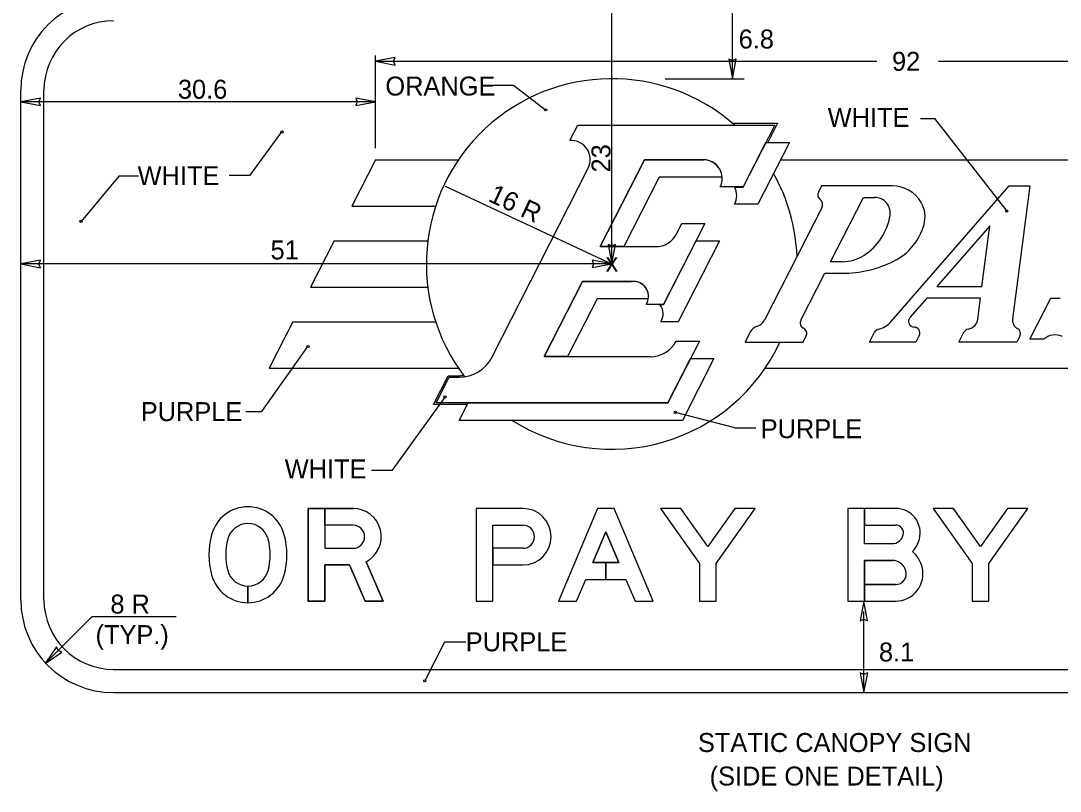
# Model space of a CAD drawing. Extents: x 319706 to 320449, y 1621775 to 1622117.
# Drawn here: x 319821.8 to 319898.5, y 1621852.1 to 1621908.9 of the extents above; entities that cross this region are included whole.
import ezdxf

# ---------------------------------------------------------------- set-up
doc = ezdxf.new("R2010")
doc.units = 0
for name, color, linetype in [('1', 7, 'Continuous'), ('52', 7, 'Continuous'), ('GSBWFill', 7, 'Continuous'), ('GSColorFill', 7, 'Continuous'), ('GSOutline', 7, 'Continuous'), ('SignPanel', 7, 'Continuous')]:
    doc.layers.add(name, color=color, linetype=linetype)

msp = doc.modelspace()

# ---------------------------------------------------------------- linework, layer by layer
at = {"layer": '1'}
for p, q in [((319865.435, 1621890.975), (319865.435, 1621910.64)), ((319874.341, 1621904.654), (319874.341, 1621910.639)), ((319847.993, 1621899.525), (319847.993, 1621906.365)), ((319847.993, 1621905.938), (319884.997, 1621905.938)), ((319889.548, 1621905.938), (319926.653, 1621905.938)), ((319869.368, 1621904.654), (319875.196, 1621904.654)), ((319856.646, 1621904.176), (319858.193, 1621904.176)), ((319858.193, 1621904.176), (319860.552, 1621902.355)), ((319847.993, 1621902.945), (319821.83, 1621902.945)), ((319888.22, 1621901.716), (319889.238, 1621901.716)), ((319889.238, 1621901.716), (319894.572, 1621894.876)), ((319838.762, 1621897.524), (319841.1, 1621900.723)), ((319829.062, 1621897.454), (319826.277, 1621894.117)), ((319830.508, 1621897.454), (319829.062, 1621897.454)), ((319837.215, 1621897.524), (319838.762, 1621897.524)), ((319865.435, 1621890.974), (319853.158, 1621896.699)), ((319850.398, 1621890.975), (319821.83, 1621890.975)), ((319865.435, 1621890.975), (319850.398, 1621890.975)), ((319839.622, 1621880.096), (319843.019, 1621884.886)), ((319849.249, 1621875.759), (319853.128, 1621881.149)), ((319838.436, 1621880.096), (319839.622, 1621880.096)), ((319874.522, 1621878.868), (319870.131, 1621880.017)), ((319874.522, 1621878.868), (319876.07, 1621878.868)), ((319847.701, 1621875.759), (319849.249, 1621875.759)), ((319884.034, 1621859.339), (319884.034, 1621865.324)), ((319823.628, 1621861.492), (319827.091, 1621864.955)), ((319827.091, 1621864.955), (319833.282, 1621864.955)), ((319853.1, 1621863.057), (319851.628, 1621860.204)), ((319854.662, 1621863.057), (319853.1, 1621863.057))]:
    msp.add_line(p, q, dxfattribs=at)
for centre in [(319860.552, 1621902.354), (319841.1, 1621900.722), (319894.571, 1621894.875), (319826.277, 1621894.116), (319843.019, 1621884.884), (319853.128, 1621881.148), (319870.131, 1621880.015), (319870.131, 1621880.015), (319851.628, 1621860.204)]:
    msp.add_circle(centre, 0.0855, dxfattribs=at)
at = {"layer": '52'}
for p, q in [((319849.443, 1621906.208), (319847.993, 1621905.938)), ((319847.993, 1621905.938), (319849.443, 1621905.658)), ((319849.333, 1621905.938), (319849.443, 1621906.208)), ((319849.443, 1621905.658), (319849.333, 1621905.938)), ((319874.341, 1621905.994), (319874.071, 1621906.104)), ((319874.071, 1621906.104), (319874.341, 1621904.654)), ((319874.341, 1621904.654), (319874.621, 1621906.104)), ((319874.621, 1621906.104), (319874.341, 1621905.994)), ((319823.28, 1621903.215), (319821.83, 1621902.945)), ((319821.83, 1621902.945), (319823.28, 1621902.665)), ((319823.17, 1621902.945), (319823.28, 1621903.215)), ((319823.28, 1621902.665), (319823.17, 1621902.945)), ((319847.993, 1621902.945), (319846.543, 1621903.225)), ((319846.543, 1621903.225), (319846.653, 1621902.945)), ((319846.653, 1621902.945), (319846.543, 1621902.675)), ((319846.543, 1621902.675), (319847.993, 1621902.945)), ((319865.435, 1621892.315), (319865.165, 1621892.425)), ((319865.165, 1621892.425), (319865.435, 1621890.975)), ((319865.435, 1621890.975), (319865.715, 1621892.425)), ((319865.715, 1621892.425), (319865.435, 1621892.315)), ((319823.28, 1621891.245), (319821.83, 1621890.975)), ((319823.17, 1621890.975), (319823.28, 1621891.245)), ((319865.435, 1621890.975), (319863.985, 1621891.255)), ((319863.985, 1621891.255), (319864.095, 1621890.975)), ((319821.83, 1621890.975), (319823.28, 1621890.695)), ((319823.28, 1621890.695), (319823.17, 1621890.975)), ((319864.095, 1621890.975), (319863.985, 1621890.705)), ((319863.985, 1621890.705), (319865.435, 1621890.975)), ((319884.034, 1621866.088), (319883.754, 1621864.638)), ((319884.304, 1621864.638), (319884.034, 1621866.088)), ((319883.754, 1621864.638), (319884.034, 1621864.748)), ((319884.034, 1621864.748), (319884.304, 1621864.638)), ((319824.463, 1621862.708), (319823.628, 1621861.492)), ((319823.628, 1621861.492), (319824.851, 1621862.32)), ((319824.576, 1621862.44), (319824.463, 1621862.708)), ((319824.851, 1621862.32), (319824.576, 1621862.44)), ((319884.034, 1621860.679), (319883.764, 1621860.789)), ((319883.764, 1621860.789), (319884.034, 1621859.339)), ((319884.034, 1621859.339), (319884.314, 1621860.789)), ((319884.314, 1621860.789), (319884.034, 1621860.679))]:
    msp.add_line(p, q, dxfattribs=at)
at = {"layer": 'GSBWFill'}
for p, q in [((319856.649, 1621871.698), (319858.873, 1621871.698)), ((319838.587, 1621867.199), (319838.587, 1621865.968)), ((319838.588, 1621865.968), (319838.588, 1621867.199))]:
    msp.add_line(p, q, dxfattribs=at)
for points in [[(319847.316, 1621868.997), (319848.576, 1621866.088), (319847.234, 1621866.088), (319846.079, 1621868.756), (319844.266, 1621868.756), (319844.266, 1621866.088), (319843.034, 1621866.088), (319843.034, 1621872.929), (319844.266, 1621872.929), (319844.266, 1621869.987), (319846.342, 1621869.987)], [(319844.266, 1621871.698), (319844.266, 1621872.929), (319846.342, 1621872.929)], [(319858.873, 1621872.929), (319855.418, 1621872.929), (319855.418, 1621866.088), (319856.649, 1621866.088), (319856.649, 1621871.698)], [(319886.111, 1621870.329), (319884.084, 1621870.329), (319884.084, 1621872.929), (319882.852, 1621872.929), (319882.852, 1621866.088), (319884.084, 1621866.088)], [(319886.376, 1621872.929), (319884.084, 1621872.929), (319884.084, 1621871.698), (319886.376, 1621871.698)], [(319846.342, 1621871.698), (319844.266, 1621871.698)], [(319858.873, 1621869.987), (319856.649, 1621869.987), (319856.649, 1621868.756), (319858.873, 1621868.756)], [(319884.084, 1621866.088), (319884.084, 1621869.098), (319886.111, 1621869.098)], [(319886.376, 1621867.319), (319884.084, 1621867.319), (319884.084, 1621866.088), (319886.376, 1621866.088)]]:
    msp.add_lwpolyline(points, dxfattribs=at)
for points in [[(319865.957, 1621868.927), (319864.996, 1621868.927), (319864.996, 1621867.695), (319866.474, 1621867.695), (319867.149, 1621866.088), (319868.485, 1621866.088), (319865.612, 1621872.929), (319864.38, 1621872.929), (319861.507, 1621866.088), (319862.842, 1621866.088), (319863.518, 1621867.695), (319864.996, 1621867.695), (319864.996, 1621868.927), (319864.035, 1621868.927), (319864.996, 1621871.215)], [(319873.137, 1621868.858), (319876.011, 1621872.929), (319874.503, 1621872.929), (319872.522, 1621870.122), (319870.54, 1621872.929), (319869.032, 1621872.929), (319871.906, 1621868.858), (319871.906, 1621866.088), (319873.137, 1621866.088)], [(319893.251, 1621868.858), (319896.125, 1621872.929), (319894.618, 1621872.929), (319892.636, 1621870.122), (319890.654, 1621872.929), (319889.147, 1621872.929), (319892.02, 1621868.858), (319892.02, 1621866.088), (319893.251, 1621866.088)]]:
    msp.add_lwpolyline(points, close=True, dxfattribs=at)
for centre, radius, start, end in [((319838.587, 1621870.276), 2.773, 14.96177, 165.03823), ((319846.342, 1621870.843), 2.087, 297.837, 90), ((319886.376, 1621871.116), 1.813, 345.52249, 90), ((319838.587, 1621870.276), 1.541, 14.96177, 165.03823), ((319846.342, 1621870.843), 0.855, 270, 90), ((319886.376, 1621871.116), 0.582, 345.52249, 90), ((319841.461, 1621869.508), 5.747, 165.03823, 194.96177), ((319841.461, 1621869.508), 4.515, 165.03823, 194.96177), ((319835.714, 1621869.508), 4.515, 345.03823, 14.96177), ((319835.714, 1621869.508), 5.747, 345.03823, 14.96177), ((319886.111, 1621871.185), 0.855, 270, 345.52249), ((319886.111, 1621871.185), 2.087, 316.7114, 345.52249), ((319886.111, 1621868.037), 2.292, 14.47751, 48.4921), ((319886.111, 1621868.037), 1.06, 14.47751, 90), ((319838.587, 1621868.741), 1.541, 194.96177, 270), ((319838.587, 1621868.741), 1.541, 270.01272, 345.03823), ((319886.376, 1621868.106), 2.018, 270, 14.47751), ((319886.376, 1621868.106), 0.787, 270, 14.47751), ((319838.587, 1621868.741), 2.773, 194.96177, 270), ((319838.587, 1621868.741), 2.773, 270.00707, 345.03823)]:
    msp.add_arc(centre, radius, start, end, dxfattribs=at)
for major_axis in [(0, 2.087), (0, 0.855)]:
    msp.add_ellipse((319858.873, 1621870.843), major_axis=major_axis, ratio=0.999994, start_param=3.141593, end_param=6.283185, dxfattribs=at)
at = {"layer": 'GSColorFill'}
for p, q in [((319856.649, 1621871.698), (319858.873, 1621871.698)), ((319838.587, 1621867.199), (319838.587, 1621865.968)), ((319838.588, 1621865.968), (319838.588, 1621867.199))]:
    msp.add_line(p, q, dxfattribs=at)
for points in [[(319847.316, 1621868.997), (319848.576, 1621866.088), (319847.234, 1621866.088), (319846.079, 1621868.756), (319844.266, 1621868.756), (319844.266, 1621866.088), (319843.034, 1621866.088), (319843.034, 1621872.929), (319844.266, 1621872.929), (319844.266, 1621869.987), (319846.342, 1621869.987)], [(319844.266, 1621871.698), (319844.266, 1621872.929), (319846.342, 1621872.929)], [(319858.873, 1621872.929), (319855.418, 1621872.929), (319855.418, 1621866.088), (319856.649, 1621866.088), (319856.649, 1621871.698)], [(319886.111, 1621870.329), (319884.084, 1621870.329), (319884.084, 1621872.929), (319882.852, 1621872.929), (319882.852, 1621866.088), (319884.084, 1621866.088)], [(319886.376, 1621872.929), (319884.084, 1621872.929), (319884.084, 1621871.698), (319886.376, 1621871.698)], [(319846.342, 1621871.698), (319844.266, 1621871.698)], [(319858.873, 1621869.987), (319856.649, 1621869.987), (319856.649, 1621868.756), (319858.873, 1621868.756)], [(319884.084, 1621866.088), (319884.084, 1621869.098), (319886.111, 1621869.098)], [(319886.376, 1621867.319), (319884.084, 1621867.319), (319884.084, 1621866.088), (319886.376, 1621866.088)]]:
    msp.add_lwpolyline(points, dxfattribs=at)
for points in [[(319865.957, 1621868.927), (319864.996, 1621868.927), (319864.996, 1621867.695), (319866.474, 1621867.695), (319867.149, 1621866.088), (319868.485, 1621866.088), (319865.612, 1621872.929), (319864.38, 1621872.929), (319861.507, 1621866.088), (319862.842, 1621866.088), (319863.518, 1621867.695), (319864.996, 1621867.695), (319864.996, 1621868.927), (319864.035, 1621868.927), (319864.996, 1621871.215)], [(319873.137, 1621868.858), (319876.011, 1621872.929), (319874.503, 1621872.929), (319872.522, 1621870.122), (319870.54, 1621872.929), (319869.032, 1621872.929), (319871.906, 1621868.858), (319871.906, 1621866.088), (319873.137, 1621866.088)], [(319893.251, 1621868.858), (319896.125, 1621872.929), (319894.618, 1621872.929), (319892.636, 1621870.122), (319890.654, 1621872.929), (319889.147, 1621872.929), (319892.02, 1621868.858), (319892.02, 1621866.088), (319893.251, 1621866.088)]]:
    msp.add_lwpolyline(points, close=True, dxfattribs=at)
for centre, radius, start, end in [((319838.587, 1621870.276), 2.773, 14.96177, 165.03823), ((319846.342, 1621870.843), 2.087, 297.837, 90), ((319886.376, 1621871.116), 1.813, 345.52249, 90), ((319838.587, 1621870.276), 1.541, 14.96177, 165.03823), ((319846.342, 1621870.843), 0.855, 270, 90), ((319886.376, 1621871.116), 0.582, 345.52249, 90), ((319841.461, 1621869.508), 5.747, 165.03823, 194.96177), ((319841.461, 1621869.508), 4.515, 165.03823, 194.96177), ((319835.714, 1621869.508), 4.515, 345.03823, 14.96177), ((319835.714, 1621869.508), 5.747, 345.03823, 14.96177), ((319886.111, 1621871.185), 0.855, 270, 345.52249), ((319886.111, 1621871.185), 2.087, 316.7114, 345.52249), ((319886.111, 1621868.037), 2.292, 14.47751, 48.4921), ((319886.111, 1621868.037), 1.06, 14.47751, 90), ((319838.587, 1621868.741), 1.541, 194.96177, 270), ((319838.587, 1621868.741), 1.541, 270.01272, 345.03823), ((319886.376, 1621868.106), 2.018, 270, 14.47751), ((319886.376, 1621868.106), 0.787, 270, 14.47751), ((319838.587, 1621868.741), 2.773, 194.96177, 270), ((319838.587, 1621868.741), 2.773, 270.00707, 345.03823)]:
    msp.add_arc(centre, radius, start, end, dxfattribs=at)
for major_axis in [(0, 2.087), (0, 0.855)]:
    msp.add_ellipse((319858.873, 1621870.843), major_axis=major_axis, ratio=0.999994, start_param=3.141593, end_param=6.283185, dxfattribs=at)
at = {"layer": 'GSOutline'}
for p, q in [((319856.649, 1621871.698), (319858.873, 1621871.698)), ((319856.649, 1621868.756), (319858.873, 1621868.756)), ((319882.852, 1621866.088), (319886.376, 1621866.088))]:
    msp.add_line(p, q, dxfattribs=at)
for points in [[(319846.342, 1621872.929), (319843.034, 1621872.929), (319843.034, 1621866.088), (319844.266, 1621866.088), (319844.266, 1621868.756), (319846.079, 1621868.756), (319847.234, 1621866.088), (319848.576, 1621866.088), (319847.316, 1621868.997)], [(319858.873, 1621872.929), (319855.418, 1621872.929), (319855.418, 1621866.088), (319856.649, 1621866.088), (319856.649, 1621868.756)], [(319886.376, 1621872.929), (319882.852, 1621872.929), (319882.852, 1621866.088)], [(319846.342, 1621871.698), (319844.266, 1621871.698), (319844.266, 1621869.987), (319846.342, 1621869.987)], [(319858.873, 1621869.987), (319856.649, 1621869.987), (319856.649, 1621871.698)], [(319886.111, 1621870.329), (319884.084, 1621870.329), (319884.084, 1621871.698), (319886.376, 1621871.698)], [(319886.111, 1621869.098), (319884.084, 1621869.098), (319884.084, 1621867.319), (319886.376, 1621867.319)]]:
    msp.add_lwpolyline(points, dxfattribs=at)
for points in [[(319863.518, 1621867.695), (319866.474, 1621867.695), (319867.149, 1621866.088), (319868.485, 1621866.088), (319865.612, 1621872.929), (319864.38, 1621872.929), (319861.507, 1621866.088), (319862.842, 1621866.088)], [(319873.137, 1621868.858), (319876.011, 1621872.929), (319874.503, 1621872.929), (319872.522, 1621870.122), (319870.54, 1621872.929), (319869.032, 1621872.929), (319871.906, 1621868.858), (319871.906, 1621866.088), (319873.137, 1621866.088)], [(319893.251, 1621868.858), (319896.125, 1621872.929), (319894.618, 1621872.929), (319892.636, 1621870.122), (319890.654, 1621872.929), (319889.147, 1621872.929), (319892.02, 1621868.858), (319892.02, 1621866.088), (319893.251, 1621866.088)], [(319865.957, 1621868.927), (319864.996, 1621871.215), (319864.035, 1621868.927)]]:
    msp.add_lwpolyline(points, close=True, dxfattribs=at)
for centre, radius, start, end in [((319838.587, 1621870.276), 2.773, 14.96177, 165.03823), ((319846.342, 1621870.843), 2.087, 297.837, 90), ((319886.376, 1621871.116), 1.813, 345.52249, 90), ((319838.587, 1621870.276), 1.541, 14.96177, 165.03823), ((319846.342, 1621870.843), 0.855, 270, 90), ((319886.376, 1621871.116), 0.582, 345.52249, 90), ((319841.461, 1621869.508), 5.747, 165.03823, 194.96177), ((319841.461, 1621869.508), 4.515, 165.03823, 194.96177), ((319835.714, 1621869.508), 4.515, 345.03823, 14.96177), ((319835.714, 1621869.508), 5.747, 345.03823, 14.96177), ((319886.111, 1621871.185), 0.855, 270, 345.52249), ((319886.111, 1621871.185), 2.087, 316.7114, 345.52249), ((319886.111, 1621868.037), 2.292, 14.47751, 48.4921), ((319886.111, 1621868.037), 1.06, 14.47751, 90), ((319838.587, 1621868.741), 1.541, 194.96177, 345.03823), ((319886.376, 1621868.106), 2.018, 270, 14.47751), ((319886.376, 1621868.106), 0.787, 270, 14.47751), ((319838.587, 1621868.741), 2.773, 194.96177, 345.03823)]:
    msp.add_arc(centre, radius, start, end, dxfattribs=at)
for major_axis in [(0, 2.087), (0, 0.855)]:
    msp.add_ellipse((319858.873, 1621870.843), major_axis=major_axis, ratio=0.999994, start_param=3.141593, end_param=6.283185, dxfattribs=at)
at = {"layer": 'SignPanel'}
for p, q in [((319821.83, 1621866.179), (319821.83, 1621903.799)), ((319823.54, 1621866.179), (319823.54, 1621903.799)), ((319862.341, 1621900.087), (319862.924, 1621901.234)), ((319862.924, 1621901.234), (319877.459, 1621901.234)), ((319874.335, 1621901.362), (319877.668, 1621901.362)), ((319877.459, 1621901.234), (319875.131, 1621896.663)), ((319877.668, 1621901.362), (319876.949, 1621899.952)), ((319875.128, 1621896.658), (319876.807, 1621899.952)), ((319875.128, 1621896.658), (319876.807, 1621899.952)), ((319878.534, 1621899.952), (319876.204, 1621895.38)), ((319878.534, 1621899.952), (319876.204, 1621895.38)), ((319876.807, 1621899.952), (319878.534, 1621899.952)), ((319876.807, 1621899.952), (319878.534, 1621899.952)), ((319847.993, 1621898.669), (319846.252, 1621895.249)), ((319847.993, 1621898.669), (319854.124, 1621898.669)), ((319867.85, 1621898.669), (319864.583, 1621892.257)), ((319864.583, 1621892.257), (319867.85, 1621898.669)), ((319864.583, 1621892.257), (319867.85, 1621898.669)), ((319872.208, 1621898.669), (319867.85, 1621898.669)), ((319867.85, 1621898.669), (319872.208, 1621898.669)), ((319867.85, 1621898.669), (319872.208, 1621898.669)), ((319877.879, 1621898.669), (319926.653, 1621898.669)), ((319856.596, 1621884.112), (319863.692, 1621898.04)), ((319868.924, 1621897.387), (319866.31, 1621892.257)), ((319868.924, 1621897.387), (319866.31, 1621892.257)), ((319873.575, 1621897.387), (319868.924, 1621897.387)), ((319873.575, 1621897.387), (319868.924, 1621897.387)), ((319875.131, 1621896.663), (319873.42, 1621896.663)), ((319874.492, 1621896.658), (319875.128, 1621896.658)), ((319874.492, 1621896.658), (319875.128, 1621896.658)), ((319880.91, 1621896.745), (319880.677, 1621896.289)), ((319886.146, 1621896.745), (319880.91, 1621896.745)), ((319886.015, 1621886.704), (319894.746, 1621896.745)), ((319894.746, 1621896.745), (319896.285, 1621896.745)), ((319896.285, 1621896.745), (319895.005, 1621886.906)), ((319881.581, 1621891.145), (319884, 1621895.89)), ((319884, 1621895.89), (319884.824, 1621895.89)), ((319846.252, 1621895.249), (319852.44, 1621895.249)), ((319876.204, 1621895.38), (319874.494, 1621895.38)), ((319876.204, 1621895.38), (319874.494, 1621895.38)), ((319880.925, 1621895.129), (319876.691, 1621886.821)), ((319872.303, 1621893.967), (319869.254, 1621887.982)), ((319870.197, 1621893.19), (319870.593, 1621893.967)), ((319870.593, 1621893.967), (319872.303, 1621893.967)), ((319893.314, 1621893.796), (319889.411, 1621889.306)), ((319892.73, 1621889.306), (319893.314, 1621893.796)), ((319844.947, 1621892.684), (319843.206, 1621889.264)), ((319844.947, 1621892.684), (319851.861, 1621892.684)), ((319864.583, 1621892.257), (319868.674, 1621892.257)), ((319866.31, 1621892.257), (319864.583, 1621892.257)), ((319866.31, 1621892.257), (319864.583, 1621892.257)), ((319869.254, 1621887.982), (319871.65, 1621892.684)), ((319869.254, 1621887.982), (319871.65, 1621892.684)), ((319873.377, 1621892.684), (319870.327, 1621886.699)), ((319873.377, 1621892.684), (319870.327, 1621886.699)), ((319871.65, 1621892.684), (319873.377, 1621892.684)), ((319871.65, 1621892.684), (319873.377, 1621892.684)), ((319882.428, 1621891.145), (319881.581, 1621891.145)), ((319863.277, 1621889.692), (319860.445, 1621884.134)), ((319860.445, 1621884.134), (319863.277, 1621889.692)), ((319860.445, 1621884.134), (319863.277, 1621889.692)), ((319867.029, 1621889.692), (319863.277, 1621889.692)), ((319863.277, 1621889.692), (319866.868, 1621889.68)), ((319863.277, 1621889.692), (319866.868, 1621889.68)), ((319879.377, 1621886.821), (319881.145, 1621890.29)), ((319881.145, 1621890.29), (319882.428, 1621890.29)), ((319843.206, 1621889.264), (319851.861, 1621889.264)), ((319889.411, 1621889.306), (319892.73, 1621889.306)), ((319864.349, 1621888.406), (319862.172, 1621884.134)), ((319864.349, 1621888.406), (319862.172, 1621884.134)), ((319868.124, 1621888.394), (319864.349, 1621888.406)), ((319868.124, 1621888.394), (319864.349, 1621888.406)), ((319888.67, 1621888.451), (319887.43, 1621887.027)), ((319892.643, 1621888.451), (319888.67, 1621888.451)), ((319892.44, 1621886.906), (319892.643, 1621888.451)), ((319896.279, 1621885.417), (319897.831, 1621888.464)), ((319897.831, 1621888.464), (319898.518, 1621888.464)), ((319869.254, 1621887.982), (319867.966, 1621887.982)), ((319868.985, 1621887.982), (319869.254, 1621887.982)), ((319868.985, 1621887.982), (319869.254, 1621887.982)), ((319841.9, 1621886.699), (319840.159, 1621883.279)), ((319841.9, 1621886.699), (319852.44, 1621886.699)), ((319870.327, 1621886.699), (319869.045, 1621886.699)), ((319870.327, 1621886.699), (319869.045, 1621886.699)), ((319875.652, 1621885.957), (319875.268, 1621885.202)), ((319884.442, 1621885.202), (319884.814, 1621885.934)), ((319891.04, 1621885.202), (319891.418, 1621885.945)), ((319871.899, 1621885.285), (319869.57, 1621880.714)), ((319870.188, 1621885.285), (319871.899, 1621885.285)), ((319875.268, 1621885.202), (319879.543, 1621885.202)), ((319879.543, 1621885.202), (319879.775, 1621885.66)), ((319887.862, 1621885.202), (319884.442, 1621885.202)), ((319888.114, 1621885.696), (319887.862, 1621885.202)), ((319895.315, 1621885.202), (319891.04, 1621885.202)), ((319895.54, 1621885.643), (319895.315, 1621885.202)), ((319897.318, 1621885.417), (319896.279, 1621885.417)), ((319860.445, 1621884.134), (319868.292, 1621884.134)), ((319862.172, 1621884.134), (319860.445, 1621884.134)), ((319862.172, 1621884.134), (319860.445, 1621884.134)), ((319869.57, 1621880.714), (319871.245, 1621884.003)), ((319869.57, 1621880.714), (319871.245, 1621884.003)), ((319872.973, 1621884.003), (319870.643, 1621879.432)), ((319872.973, 1621884.003), (319870.643, 1621879.432)), ((319871.245, 1621884.003), (319872.973, 1621884.003)), ((319871.245, 1621884.003), (319872.973, 1621884.003)), ((319840.159, 1621883.279), (319854.124, 1621883.279)), ((319876.745, 1621883.279), (319918.811, 1621883.279)), ((319852.287, 1621880.602), (319853.371, 1621882.73)), ((319852.47, 1621880.714), (319853.44, 1621882.618)), ((319853.371, 1621882.73), (319854.158, 1621882.73)), ((319853.44, 1621882.618), (319854.158, 1621882.618)), ((319854.776, 1621880.602), (319852.287, 1621880.602)), ((319869.57, 1621880.714), (319852.47, 1621880.714)), ((319854.18, 1621879.432), (319854.833, 1621880.714)), ((319854.18, 1621879.432), (319854.833, 1621880.714)), ((319854.833, 1621880.714), (319869.57, 1621880.714)), ((319854.833, 1621880.714), (319869.57, 1621880.714)), ((319870.643, 1621879.432), (319854.18, 1621879.432)), ((319870.643, 1621879.432), (319854.18, 1621879.432)), ((319828.67, 1621861.049), (319938.11, 1621861.049)), ((319828.67, 1621859.339), (319938.11, 1621859.339))]:
    msp.add_line(p, q, dxfattribs=at)
for centre, radius, start, end in [((319828.67, 1621903.798), 6.84, 90, 180), ((319828.67, 1621903.798), 5.13, 90, 180), ((319865.435, 1621890.973), 13.68, 48.59038, 217.4727), ((319862.434, 1621898.679), 1.411, 332.99985, 93.80449), ((319872.209, 1621897.3), 1.368, 332.20885, 90), ((319872.209, 1621897.3), 1.368, 3.58332, 90), ((319872.209, 1621897.3), 1.368, 3.58332, 90), ((319865.435, 1621890.973), 13.68, 2.42356, 29.27706), ((319873.283, 1621896.017), 1.368, 332.20885, 27.91266), ((319873.283, 1621896.017), 1.368, 332.20885, 27.91266), ((319886.146, 1621894.307), 2.437, 29.43149, 90), ((319881.057, 1621896.094), 0.428, 152.97842, 231.16017), ((319884.823, 1621894.735), 1.154, 351.07601, 90), ((319880.468, 1621895.361), 0.513, 333.00266, 51.16017), ((319886.407, 1621894.454), 2.138, 344.70738, 29.43149), ((319881.74, 1621895.219), 4.275, 302.42062, 351.07601), ((319884.345, 1621895.018), 4.275, 296.64315, 344.70738), ((319868.674, 1621893.965), 1.71, 270, 332.98829), ((319882.428, 1621894.136), 2.993, 270, 302.42062), ((319882.428, 1621898.839), 8.55, 270, 296.64315), ((319867.029, 1621888.579), 1.111, 350.35016, 98.33436), ((319867.029, 1621888.579), 1.111, 350.35016, 98.33436), ((319867.029, 1621888.579), 1.111, 327.42103, 90), ((319868.109, 1621887.296), 1.111, 327.42103, 37.97987), ((319868.109, 1621887.296), 1.111, 327.42103, 37.97987), ((319875.93, 1621887.208), 0.855, 286.43167, 332.99588), ((319879.758, 1621886.626), 0.427, 152.98839, 244.78323), ((319884.725, 1621887.824), 1.71, 282.71621, 318.99659), ((319887.753, 1621886.745), 0.427, 138.98241, 268.68694), ((319891.593, 1621887.016), 0.855, 279.2397, 352.56317), ((319895.683, 1621886.817), 0.684, 172.58839, 241.86732), ((319876.414, 1621885.567), 0.855, 106.43168, 152.97425), ((319879.394, 1621885.853), 0.427, 333.02391, 64.78322), ((319885.195, 1621885.739), 0.427, 102.71621, 153.02391), ((319887.733, 1621885.89), 0.427, 332.97842, 88.68694), ((319891.799, 1621885.75), 0.428, 99.2397, 153.02391), ((319895.159, 1621885.836), 0.427, 332.97842, 61.86732), ((319865.435, 1621890.973), 13.68, 237.53826, 335.04698), ((319868.292, 1621886.27), 2.138, 270, 332.5096), ((319898.137, 1621884.543), 1.197, 64.37946, 133.18921), ((319854.158, 1621885.354), 2.736, 270, 332.99913), ((319854.158, 1621885.354), 2.625, 270, 277.50379), ((319828.67, 1621866.178), 6.84, 180, 270), ((319828.67, 1621866.178), 5.13, 180, 270)]:
    msp.add_arc(centre, radius, start, end, dxfattribs=at)

# ---------------------------------------------------------------- texts
at = {"layer": '1'}
for s, p in [('6.8', (319874.795, 1621906.884)), ('92', (319886.109, 1621905.237)), ('30.6', (319833.422, 1621903.175)), ('ORANGE', (319848.731, 1621903.41)), ('WHITE', (319881.364, 1621901.098)), ('WHITE', (319830.45, 1621896.795)), ('51', (319840.256, 1621891.312)), ('x', (319864.974, 1621890.402)), ('PURPLE', (319830.682, 1621879.379)), ('PURPLE', (319876.42, 1621878.115)), ('WHITE', (319841.303, 1621875.147)), ('8 R', (319828.439, 1621865.169)), ('(TYP.)', (319827.343, 1621862.914)), ('PURPLE', (319854.658, 1621862.385)), ('8.1', (319885.146, 1621861.632)), ('STATIC CANOPY SIGN', (319871.791, 1621854.95)), ('(SIDE ONE DETAIL)', (319872.655, 1621852.476))]:
    msp.add_text(s, height=1.4, dxfattribs=at).set_placement(p)
for s, rotation, p in [('23', 90, (319865.338, 1621897.733)), ('16 R', 334.99906, (319856.242, 1621895.645))]:
    msp.add_text(s, height=1.4, rotation=rotation, dxfattribs=at).set_placement(p)

doc.saveas('drawing.dxf')
